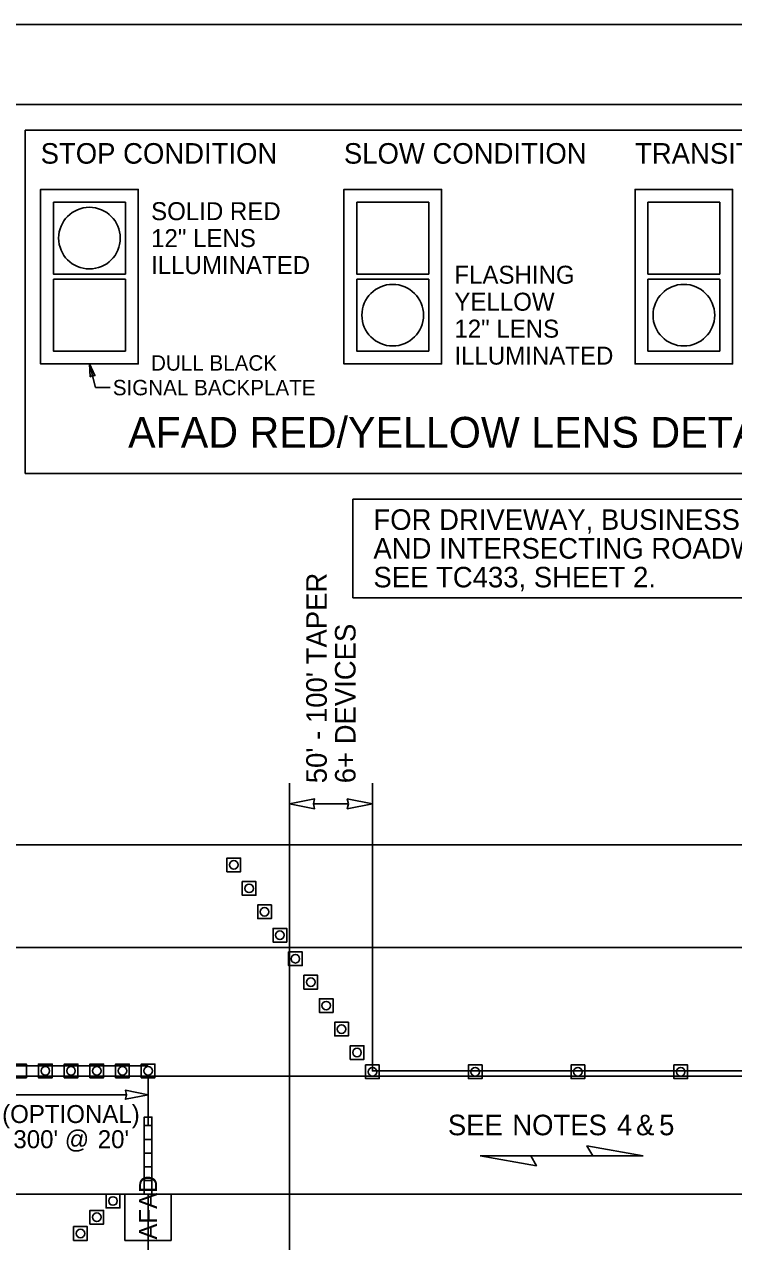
# Model space of a CAD drawing. Extents: x 99999.1 to 100095.7, y 99995 to 100010.7.
# Drawn here: x 100003.795 to 100006.556, y 100005.947 to 100010.687 of the extents above; entities that cross this region are included whole.
import ezdxf

# ---------------------------------------------------------------- set-up
doc = ezdxf.new("R2010")
doc.units = 0
for name, color, linetype in [('RD_ED_ShoulderPavedEdge', 7, 'Continuous'), ('RD_MK_LineEdgeWhite', 7, 'Continuous'), ('RD_MK_LineNoPass', 7, 'Continuous'), ('RD_MK_LineSkipCenter', 7, 'Continuous'), ('SH_GI_PlotLimits', 7, 'Continuous'), ('SH_GI_SheetBorder', 7, 'Continuous'), ('SH_TI_Tables', 7, 'Continuous'), ('TR_WZ_AFAD', 7, 'Continuous'), ('TR_WZ_TrafficCone', 7, 'Continuous'), ('TR_WZ_WorkZoneDetails', 7, 'Continuous'), ('TR_WZ_WorkZoneTextCurrent', 7, 'Continuous')]:
    doc.layers.add(name, color=color, linetype=linetype)

msp = doc.modelspace()

# ---------------------------------------------------------------- linework, layer by layer
at = {"layer": 'RD_ED_ShoulderPavedEdge'}
msp.add_line((100000.1076, 100007.4923), (100015.6424, 100007.4923), dxfattribs=at)
at = {"layer": 'RD_MK_LineEdgeWhite'}
for p, q in [((100000.1076, 100007.0923), (100015.6424, 100007.0923)), ((100000.1076, 100006.1323), (100015.6424, 100006.1323))]:
    msp.add_line(p, q, dxfattribs=at)
at = {"layer": 'RD_MK_LineNoPass'}
msp.add_line((100003.4767, 100006.6323), (100004.2767, 100006.6323), dxfattribs=at)
at = {"layer": 'RD_MK_LineSkipCenter'}
msp.add_lwpolyline([(100011.15, 100006.5923), (100003.4767, 100006.5923)], dxfattribs=at)
at = {"layer": 'SH_GI_PlotLimits'}
msp.add_lwpolyline([(99999.0625, 99999.6875), (100016.0625, 99999.6875), (100016.0625, 100010.6875), (99999.0625, 100010.6875)], close=True, dxfattribs=at)
at = {"layer": 'SH_GI_SheetBorder'}
msp.add_line((100000, 100010.375), (100015.75, 100010.375), dxfattribs=at)
at = {"layer": 'SH_TI_Tables'}
msp.add_lwpolyline([(100005.0739, 100008.839), (100007.5374, 100008.839), (100007.5374, 100008.455), (100005.0739, 100008.455)], close=True, dxfattribs=at)
at = {"layer": 'TR_WZ_AFAD'}
for p, q in [((100004.2916, 100006.399), (100004.2916, 100006.4323)), ((100004.2616, 100006.399), (100004.2616, 100006.3457)), ((100004.2616, 100006.399), (100004.2766, 100006.399)), ((100004.2766, 100006.399), (100004.2916, 100006.399)), ((100004.2916, 100006.3457), (100004.2916, 100006.399)), ((100004.2616, 100006.3457), (100004.2616, 100006.2923)), ((100004.2766, 100006.3457), (100004.2616, 100006.3457)), ((100004.2916, 100006.3457), (100004.2766, 100006.3457)), ((100004.2916, 100006.2923), (100004.2916, 100006.3457)), ((100004.2616, 100006.2923), (100004.2616, 100006.239)), ((100004.2616, 100006.2923), (100004.2766, 100006.2923)), ((100004.2766, 100006.2923), (100004.2916, 100006.2923)), ((100004.2916, 100006.239), (100004.2916, 100006.2923)), ((100004.2766, 100006.239), (100004.2616, 100006.239)), ((100004.2616, 100006.239), (100004.2616, 100006.1857)), ((100004.2916, 100006.239), (100004.2766, 100006.239)), ((100004.2916, 100006.1857), (100004.2916, 100006.239)), ((100004.2616, 100006.1857), (100004.2616, 100006.1323)), ((100004.1866, 100005.9523), (100004.1866, 100006.1323)), ((100004.1866, 100006.1323), (100004.3666, 100006.1323)), ((100004.27, 100006.1323), (100004.1866, 100006.1323)), ((100004.1866, 100006.1323), (100004.1866, 100005.9523)), ((100004.2616, 100006.1323), (100004.27, 100006.1323)), ((100004.27, 100006.1323), (100004.2766, 100006.1323)), ((100004.3666, 100006.1323), (100004.3666, 100005.9523)), ((100004.3666, 100005.9523), (100004.3666, 100006.1323)), ((100004.3666, 100005.9523), (100004.1866, 100005.9523)), ((100004.1866, 100005.9523), (100004.3666, 100005.9523))]:
    msp.add_line(p, q, dxfattribs=at)
for points in [[(100004.2916, 100006.4323), (100004.2616, 100006.4323), (100004.2616, 100006.399)], [(100004.2916, 100006.1323), (100004.2916, 100006.4323), (100004.2616, 100006.4323), (100004.2616, 100006.1323)], [(100004.2916, 100006.399), (100004.2766, 100006.399), (100004.2616, 100006.399)], [(100004.2616, 100006.3457), (100004.2766, 100006.3457), (100004.2916, 100006.3457)], [(100004.2916, 100006.2923), (100004.2766, 100006.2923), (100004.2616, 100006.2923)], [(100004.2616, 100006.239), (100004.2766, 100006.239), (100004.2916, 100006.239)], [(100004.2916, 100006.1857), (100004.2766, 100006.1857), (100004.2616, 100006.1857)], [(100004.2616, 100006.1857), (100004.2766, 100006.1857), (100004.2916, 100006.1857)], [(100004.2766, 100006.1323), (100004.2833, 100006.1323), (100004.2916, 100006.1323), (100004.2916, 100006.1857)], [(100004.3666, 100006.1323), (100004.2833, 100006.1323), (100004.27, 100006.1323)]]:
    msp.add_lwpolyline(points, dxfattribs=at)
at = {"layer": 'TR_WZ_TrafficCone'}
for points in [[(100004.6367, 100007.4411), (100004.5834, 100007.4411), (100004.5834, 100007.3877), (100004.6367, 100007.3877), (100004.6367, 100007.4411)], [(100004.6367, 100007.3877), (100004.5834, 100007.3877), (100004.5834, 100007.4411), (100004.6367, 100007.4411), (100004.6367, 100007.3877)], [(100004.6967, 100007.3497), (100004.6434, 100007.3497), (100004.6434, 100007.2964), (100004.6967, 100007.2964), (100004.6967, 100007.3497)], [(100004.6967, 100007.2964), (100004.6434, 100007.2964), (100004.6434, 100007.3497), (100004.6967, 100007.3497), (100004.6967, 100007.2964)], [(100004.7567, 100007.2584), (100004.7034, 100007.2584), (100004.7034, 100007.2051), (100004.7567, 100007.2051), (100004.7567, 100007.2584)], [(100004.7567, 100007.2051), (100004.7034, 100007.2051), (100004.7034, 100007.2584), (100004.7567, 100007.2584), (100004.7567, 100007.2051)], [(100004.8167, 100007.1671), (100004.7634, 100007.1671), (100004.7634, 100007.1137), (100004.8167, 100007.1137), (100004.8167, 100007.1671)], [(100004.8167, 100007.1137), (100004.7634, 100007.1137), (100004.7634, 100007.1671), (100004.8167, 100007.1671), (100004.8167, 100007.1137)], [(100004.8234, 100007.0757), (100004.8767, 100007.0757), (100004.8767, 100007.0224), (100004.8234, 100007.0224), (100004.8234, 100007.0757)], [(100004.8234, 100007.0224), (100004.8767, 100007.0224), (100004.8767, 100007.0757), (100004.8234, 100007.0757), (100004.8234, 100007.0224)], [(100004.8834, 100006.9844), (100004.9367, 100006.9844), (100004.9367, 100006.9311), (100004.8834, 100006.9311), (100004.8834, 100006.9844)], [(100004.8834, 100006.9311), (100004.9367, 100006.9311), (100004.9367, 100006.9844), (100004.8834, 100006.9844), (100004.8834, 100006.9311)], [(100004.9434, 100006.8931), (100004.9967, 100006.8931), (100004.9967, 100006.8397), (100004.9434, 100006.8397), (100004.9434, 100006.8931)], [(100004.9434, 100006.8397), (100004.9967, 100006.8397), (100004.9967, 100006.8931), (100004.9434, 100006.8931), (100004.9434, 100006.8397)], [(100005.0034, 100006.8017), (100005.0567, 100006.8017), (100005.0567, 100006.7484), (100005.0034, 100006.7484), (100005.0034, 100006.8017)], [(100005.0034, 100006.7484), (100005.0567, 100006.7484), (100005.0567, 100006.8017), (100005.0034, 100006.8017), (100005.0034, 100006.7484)], [(100005.0634, 100006.7104), (100005.1167, 100006.7104), (100005.1167, 100006.6571), (100005.0634, 100006.6571), (100005.0634, 100006.7104)], [(100005.0634, 100006.6571), (100005.1167, 100006.6571), (100005.1167, 100006.7104), (100005.0634, 100006.7104), (100005.0634, 100006.6571)], [(100003.8033, 100006.639), (100003.75, 100006.639), (100003.75, 100006.5857), (100003.8033, 100006.5857), (100003.8033, 100006.639)], [(100003.8033, 100006.5857), (100003.75, 100006.5857), (100003.75, 100006.639), (100003.8033, 100006.639), (100003.8033, 100006.5857)], [(100003.9033, 100006.639), (100003.85, 100006.639), (100003.85, 100006.5857), (100003.9033, 100006.5857), (100003.9033, 100006.639)], [(100003.9033, 100006.5857), (100003.85, 100006.5857), (100003.85, 100006.639), (100003.9033, 100006.639), (100003.9033, 100006.5857)], [(100004.0033, 100006.639), (100003.95, 100006.639), (100003.95, 100006.5857), (100004.0033, 100006.5857), (100004.0033, 100006.639)], [(100004.0033, 100006.5857), (100003.95, 100006.5857), (100003.95, 100006.639), (100004.0033, 100006.639), (100004.0033, 100006.5857)], [(100004.1033, 100006.639), (100004.05, 100006.639), (100004.05, 100006.5857), (100004.1033, 100006.5857), (100004.1033, 100006.639)], [(100004.1033, 100006.5857), (100004.05, 100006.5857), (100004.05, 100006.639), (100004.1033, 100006.639), (100004.1033, 100006.5857)], [(100004.2033, 100006.639), (100004.15, 100006.639), (100004.15, 100006.5857), (100004.2033, 100006.5857), (100004.2033, 100006.639)], [(100004.2033, 100006.5857), (100004.15, 100006.5857), (100004.15, 100006.639), (100004.2033, 100006.639), (100004.2033, 100006.5857)], [(100004.3033, 100006.639), (100004.25, 100006.639), (100004.25, 100006.5857), (100004.3033, 100006.5857), (100004.3033, 100006.639)], [(100004.3033, 100006.5857), (100004.25, 100006.5857), (100004.25, 100006.639), (100004.3033, 100006.639), (100004.3033, 100006.5857)], [(100005.1234, 100006.6357), (100005.1767, 100006.6357), (100005.1767, 100006.5823), (100005.1234, 100006.5823), (100005.1234, 100006.6357)], [(100005.1234, 100006.5823), (100005.1767, 100006.5823), (100005.1767, 100006.6357), (100005.1234, 100006.6357), (100005.1234, 100006.5823)], [(100005.5234, 100006.6357), (100005.5767, 100006.6357), (100005.5767, 100006.5823), (100005.5234, 100006.5823), (100005.5234, 100006.6357)], [(100005.5234, 100006.5823), (100005.5767, 100006.5823), (100005.5767, 100006.6357), (100005.5234, 100006.6357), (100005.5234, 100006.5823)], [(100005.9234, 100006.6357), (100005.9767, 100006.6357), (100005.9767, 100006.5823), (100005.9234, 100006.5823), (100005.9234, 100006.6357)], [(100005.9234, 100006.5823), (100005.9767, 100006.5823), (100005.9767, 100006.6357), (100005.9234, 100006.6357), (100005.9234, 100006.5823)], [(100006.3234, 100006.6357), (100006.3767, 100006.6357), (100006.3767, 100006.5823), (100006.3234, 100006.5823), (100006.3234, 100006.6357)], [(100006.3234, 100006.5823), (100006.3767, 100006.5823), (100006.3767, 100006.6357), (100006.3234, 100006.6357), (100006.3234, 100006.5823)], [(100004.1133, 100006.1323), (100004.1667, 100006.1323), (100004.1667, 100006.079), (100004.1133, 100006.079), (100004.1133, 100006.1323)], [(100004.1133, 100006.079), (100004.1667, 100006.079), (100004.1667, 100006.1323), (100004.1133, 100006.1323), (100004.1133, 100006.079)], [(100004.05, 100006.069), (100004.1033, 100006.069), (100004.1033, 100006.0157), (100004.05, 100006.0157), (100004.05, 100006.069)], [(100004.05, 100006.0157), (100004.1033, 100006.0157), (100004.1033, 100006.069), (100004.05, 100006.069), (100004.05, 100006.0157)], [(100003.9867, 100006.0057), (100004.04, 100006.0057), (100004.04, 100005.9523), (100003.9867, 100005.9523), (100003.9867, 100006.0057)], [(100003.9867, 100005.9523), (100004.04, 100005.9523), (100004.04, 100006.0057), (100003.9867, 100006.0057), (100003.9867, 100005.9523)]]:
    msp.add_lwpolyline(points, dxfattribs=at)
for centre in [(100004.61, 100007.4144), (100004.67, 100007.3231), (100004.73, 100007.2317), (100004.79, 100007.1404), (100004.85, 100007.0491), (100004.91, 100006.9577), (100004.97, 100006.8664), (100005.03, 100006.7751), (100005.09, 100006.6837), (100003.8767, 100006.6123), (100003.9767, 100006.6123), (100004.0767, 100006.6123), (100004.1767, 100006.6123), (100004.2767, 100006.6123), (100005.15, 100006.609), (100005.55, 100006.609), (100005.95, 100006.609), (100006.35, 100006.609), (100004.14, 100006.1057), (100004.0767, 100006.0423), (100004.0133, 100005.979)]:
    msp.add_circle(centre, 0.0167, dxfattribs=at)
at = {"layer": 'TR_WZ_WorkZoneDetails'}
for p, q in [((100004.0484, 100009.365), (100004.0723, 100009.273)), ((100004.1292, 100009.273), (100004.0723, 100009.273)), ((100004.8267, 100005.4923), (100004.8267, 100007.7323)), ((100005.15, 100007.4923), (100005.15, 100007.7323)), ((100004.9204, 100007.6523), (100005.0563, 100007.6523)), ((100004.2767, 100006.5857), (100004.2767, 100006.4023)), ((100004.1923, 100006.5193), (100003.761, 100006.5193)), ((100005.7663, 100006.2816), (100006.0074, 100006.2816)), ((100006.0074, 100006.2816), (100005.7663, 100006.2816)), ((100004.2767, 100006.1323), (100004.2767, 100005.4923))]:
    msp.add_line(p, q, dxfattribs=at)
for points in [[(100003.7984, 100010.275), (100007.5374, 100010.275), (100007.5374, 100008.939), (100003.7984, 100008.939)], [(100004.2384, 100010.045), (100003.8584, 100010.045), (100003.8584, 100009.365), (100004.2384, 100009.365)], [(100005.419, 100010.045), (100005.039, 100010.045), (100005.039, 100009.365), (100005.419, 100009.365)], [(100006.5523, 100010.045), (100006.1723, 100010.045), (100006.1723, 100009.365), (100006.5523, 100009.365)], [(100003.9084, 100009.995), (100004.1884, 100009.995), (100004.1884, 100009.715), (100003.9084, 100009.715)], [(100005.089, 100009.995), (100005.369, 100009.995), (100005.369, 100009.715), (100005.089, 100009.715)], [(100006.2223, 100009.995), (100006.5023, 100009.995), (100006.5023, 100009.715), (100006.2223, 100009.715)], [(100003.9084, 100009.695), (100004.1884, 100009.695), (100004.1884, 100009.415), (100003.9084, 100009.415)], [(100005.089, 100009.695), (100005.369, 100009.695), (100005.369, 100009.415), (100005.089, 100009.415)], [(100006.2223, 100009.695), (100006.5023, 100009.695), (100006.5023, 100009.415), (100006.2223, 100009.415)], [(100004.0484, 100009.365), (100004.07, 100009.3198), (100004.0601, 100009.3196), (100004.0514, 100009.315)], [(100004.8267, 100007.6523), (100004.9249, 100007.6331), (100004.9204, 100007.6523), (100004.9249, 100007.6716)], [(100005.15, 100007.6523), (100005.0517, 100007.6331), (100005.0563, 100007.6523), (100005.0517, 100007.6716)], [(100005.15, 100007.4923), (100005.15, 100006.6123), (100009.9338, 100006.6123), (100009.9338, 100007.4923)], [(100004.2767, 100006.5193), (100004.1882, 100006.502), (100004.1923, 100006.5193), (100004.1882, 100006.5367)], [(100005.5698, 100006.2816), (100005.7886, 100006.243), (100005.7663, 100006.2816)], [(100006.2039, 100006.2816), (100005.9851, 100006.3202), (100006.0074, 100006.2816)]]:
    msp.add_lwpolyline(points, close=True, dxfattribs=at)
for points in [[(100003.8584, 100010.045), (100004.2384, 100010.045), (100004.2384, 100009.365), (100003.8584, 100009.365), (100003.8584, 100010.045)], [(100005.039, 100010.045), (100005.419, 100010.045), (100005.419, 100009.365), (100005.039, 100009.365), (100005.039, 100010.045)], [(100006.1723, 100010.045), (100006.5523, 100010.045), (100006.5523, 100009.365), (100006.1723, 100009.365), (100006.1723, 100010.045)], [(100003.9084, 100009.995), (100004.1884, 100009.995), (100004.1884, 100009.715), (100003.9084, 100009.715), (100003.9084, 100009.995)], [(100005.089, 100009.995), (100005.369, 100009.995), (100005.369, 100009.715), (100005.089, 100009.715), (100005.089, 100009.995)], [(100006.2223, 100009.995), (100006.5023, 100009.995), (100006.5023, 100009.715), (100006.2223, 100009.715), (100006.2223, 100009.995)], [(100003.9084, 100009.695), (100004.1884, 100009.695), (100004.1884, 100009.415), (100003.9084, 100009.415), (100003.9084, 100009.695)], [(100005.089, 100009.695), (100005.369, 100009.695), (100005.369, 100009.415), (100005.089, 100009.415), (100005.089, 100009.695)], [(100006.2223, 100009.695), (100006.5023, 100009.695), (100006.5023, 100009.415), (100006.2223, 100009.415), (100006.2223, 100009.695)]]:
    msp.add_lwpolyline(points, dxfattribs=at)
for centre in [(100004.0484, 100009.855), (100005.229, 100009.555), (100006.3623, 100009.555)]:
    msp.add_circle(centre, 0.12, dxfattribs=at)

# ---------------------------------------------------------------- texts
at = {"layer": 'SH_TI_Tables'}
for s, p in [('FOR DRIVEWAY, BUSINESS ACCESS,', (100005.1539, 100008.719)), ('AND INTERSECTING ROADWAY DETAILS:', (100005.1539, 100008.607)), ('SEE TC433, SHEET 2.', (100005.1539, 100008.495))]:
    msp.add_text(s, height=0.08, rotation=360, dxfattribs=at).set_placement(p)
at = {"layer": 'TR_WZ_AFAD'}
msp.add_text('AFAD', height=0.07, rotation=90, dxfattribs=at).set_placement((100004.3116, 100005.9553))
at = {"layer": 'TR_WZ_WorkZoneDetails'}
for s, height, p in [('STOP CONDITION', 0.08, (100003.8584, 100010.145)), ('SLOW CONDITION', 0.08, (100005.039, 100010.145)), ('TRANSITION TO STOP', 0.08, (100006.1723, 100010.145)), ('SOLID RED', 0.07, (100004.2884, 100009.925)), ('12" LENS ', 0.07, (100004.2884, 100009.82)), ('ILLUMINATED', 0.07, (100004.2884, 100009.715)), ('FLASHING', 0.07, (100005.469, 100009.6775)), ('YELLOW', 0.07, (100005.469, 100009.5725)), ('12" LENS ', 0.07, (100005.469, 100009.4675)), ('ILLUMINATED', 0.07, (100005.469, 100009.3625)), ('DULL BLACK', 0.06, (100004.2881, 100009.339)), ('SIGNAL BACKPLATE', 0.06, (100004.1392, 100009.243))]:
    msp.add_text(s, height=height, dxfattribs=at).set_placement(p)
msp.add_text('AFAD RED/YELLOW LENS DETAIL', height=0.12, rotation=360, dxfattribs=at).set_placement((100004.1989, 100009.039))
at = {"layer": 'TR_WZ_WorkZoneTextCurrent'}
for s, p in [("50' - 100' TAPER", (100004.9723, 100007.7323)), ('6+ DEVICES', (100005.0843, 100007.7323))]:
    msp.add_text(s, height=0.08, rotation=90, dxfattribs=at).set_placement(p)
for s, height, p in [('(OPTIONAL)', 0.07, (100003.7085, 100006.4093)), ('SEE', 0.08, (100005.4437, 100006.3616)), ('NOTES', 0.08, (100005.6943, 100006.3616)), ('4', 0.08, (100006.1018, 100006.3616)), ('&', 0.08, (100006.1762, 100006.3616)), ('5', 0.08, (100006.266, 100006.3616)), ("300' @", 0.07, (100003.7523, 100006.3113)), ("20'", 0.07, (100004.0807, 100006.3113))]:
    msp.add_text(s, height=height, dxfattribs=at).set_placement(p)

doc.saveas('drawing.dxf')
